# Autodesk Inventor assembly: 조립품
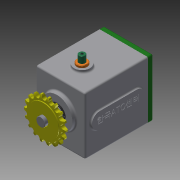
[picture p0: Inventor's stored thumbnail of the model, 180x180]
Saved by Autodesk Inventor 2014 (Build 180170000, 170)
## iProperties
Created: 2018-12
Part Number: 조립품
Document SubType Name: Assembly
Designer: kh
Author: kh
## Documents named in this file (16)
- C:\Users\kh\Desktop\381207V1059\조립품.iam
- C:\Users\kh\Desktop\381207V1059\가변스프링.ipt
- C:\Users\kh\Desktop\381207V1059\본체.ipt
- C:\Users\kh\Desktop\381207V1059\멈춤나사 M3x8.ipt
- C:\Users\kh\Desktop\381207V1059\메인 기어 축.ipt
- C:\Users\kh\Desktop\381207V1059\베어링 608.ipt
- C:\Users\kh\Desktop\381207V1059\베어링 6003.ipt
- C:\Users\kh\Desktop\381207V1059\볼트 M4 x 10.ipt
- C:\Users\kh\Desktop\381207V1059\부시.ipt
- C:\Users\kh\Desktop\381207V1059\서브 기어 축.ipt
- C:\Users\kh\Desktop\381207V1059\스프로킷.ipt
- C:\Users\kh\Desktop\381207V1059\슬라이더.ipt
- C:\Users\kh\Desktop\381207V1059\오일 실 8 22 7.ipt
- C:\Users\kh\Desktop\381207V1059\오일 실 17 32 8.ipt
- C:\Users\kh\Desktop\381207V1059\커버.ipt
- C:\Users\kh\Desktop\381207V1059\키 5 x 5 x 18.ipt
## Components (1 placed, 1 different names)
1. 가변스프링:1
